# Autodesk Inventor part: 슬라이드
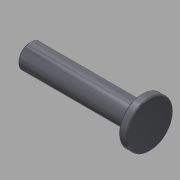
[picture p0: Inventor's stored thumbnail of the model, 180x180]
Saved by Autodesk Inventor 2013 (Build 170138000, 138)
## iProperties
Created: 2015-10
Part Number: 슬라이드
Document SubType Name: Modeling
Designer: mdu
Density: 1 g/cm^3
Material: 강철, 연강
Author: mdu
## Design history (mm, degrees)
sketch "스케치1"
  geometry: L1 (-75, 162)-(-75, 58) reference; L2 (-148, 110)-(2, 110); L3 (-148, 110)-(-148, 125); L4 (-148, 125)-(-8, 125); L5 (-8, 125)-(-8, 139); L6 (-8, 139)-(2, 139); L7 (2, 139)-(2, 110); 2 further points
  constraints: 12 end point, 3 parallel, 3 perpendicular, 1 midpoint, 1 point on line
  dimensions: "d0" = 58 diameter of L6 L2; "d1" = 30 diameter of L4 L2; "d2" = 10 distance of L5.end L6.end; "d3" = 150 distance of L2.start L2.end; "d4" = 73 distance between parallel lines of L3 L1
revolve "회전1" sketch "스케치1" stored, may be unused: angle "d5" = 90 deg
hole "구멍1" diameter "d11" = 13.376; stored, may be unused: countersink angle "d15" = 90 deg, drill point angle "d17" = 118 deg; dims "d9" = 10, "d10" = 10, "d12" = 22, "d13" = 4, "d14" = 2, "d16" = 25
chamfer "모따기1" distance "d6" = 1; stored, may be unused: second distance "d7" = 2, angle "d8" = 45 deg
node "솔리드1"
node "참조1"
